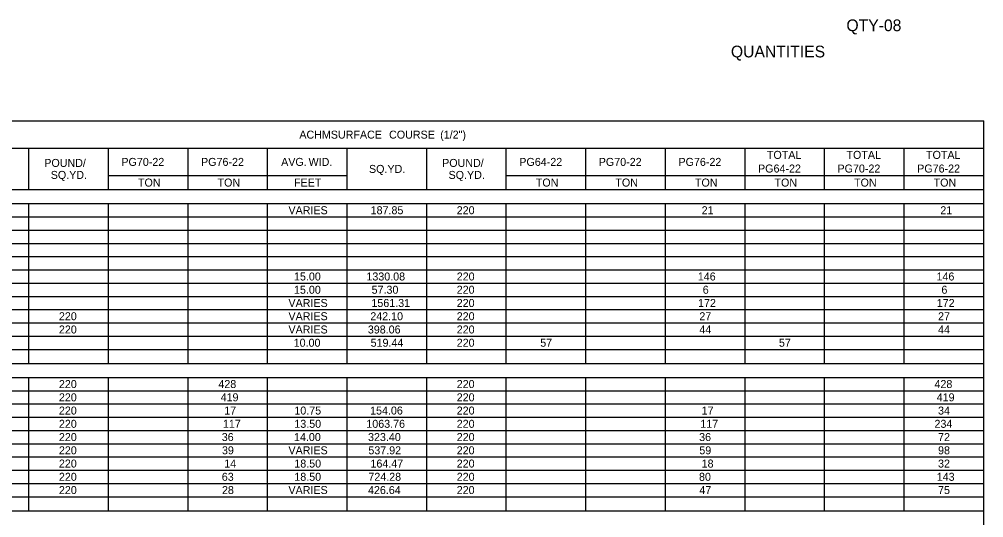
# Model space of a CAD drawing. Extents: x 1226567 to 1228151, y 151309 to 152305.
# Drawn here: x 1227669.3 to 1228150.8, y 152056.4 to 152305.5 of the extents above; entities that cross this region are included whole.
import ezdxf

# ---------------------------------------------------------------- set-up
doc = ezdxf.new("R2010")
doc.units = 0
doc.layers.add('R_Border', color=7, linetype='Continuous')
doc.layers.add('R_Dimension', color=7, linetype='Continuous')

msp = doc.modelspace()

# ---------------------------------------------------------------- linework, layer by layer
at = {"layer": 'R_Dimension'}
for p, q in [((1226566.84, 152254.68), (1228150.79, 152254.68)), ((1228150.79, 151664.64), (1228150.79, 152254.68)), ((1226879.58, 152241.04), (1228150.79, 152241.04)), ((1227674.09, 152220.4), (1227674.09, 152241.04)), ((1227713.81, 152220.4), (1227713.81, 152241.04)), ((1227753.54, 152220.4), (1227753.54, 152241.04)), ((1227793.26, 152220.4), (1227793.26, 152241.04)), ((1227832.99, 152220.4), (1227832.99, 152241.04)), ((1227872.71, 152220.4), (1227872.71, 152241.04)), ((1227912.44, 152220.4), (1227912.44, 152241.04)), ((1227952.16, 152220.4), (1227952.16, 152241.04)), ((1227991.89, 152220.4), (1227991.89, 152241.04)), ((1228031.61, 152220.4), (1228031.61, 152241.04)), ((1228071.34, 152220.4), (1228071.34, 152241.04)), ((1228111.06, 152220.4), (1228111.06, 152241.04)), ((1227713.81, 152227.41), (1227832.99, 152227.41)), ((1227912.44, 152227.41), (1228150.79, 152227.41)), ((1226566.84, 152220.4), (1228150.79, 152220.4)), ((1226566.84, 152220.4), (1228150.79, 152220.4)), ((1227634.36, 152220.4), (1227872.71, 152220.4)), ((1227832.99, 152220.4), (1228150.79, 152220.4)), ((1226566.84, 152213.39), (1228150.79, 152213.39)), ((1227674.09, 152133.55), (1227674.09, 152213.39)), ((1227713.81, 152133.55), (1227713.81, 152213.39)), ((1227753.54, 152133.55), (1227753.54, 152213.39)), ((1227793.26, 152133.55), (1227793.26, 152213.39)), ((1227832.99, 152133.55), (1227832.99, 152213.39)), ((1227872.71, 152133.55), (1227872.71, 152213.39)), ((1227912.44, 152133.55), (1227912.44, 152213.39)), ((1227952.16, 152133.55), (1227952.16, 152213.39)), ((1227991.89, 152133.55), (1227991.89, 152213.39)), ((1228031.61, 152133.55), (1228031.61, 152213.39)), ((1228071.34, 152133.55), (1228071.34, 152213.39)), ((1228111.06, 152133.55), (1228111.06, 152213.39)), ((1226566.84, 152206.77), (1228150.79, 152206.77)), ((1226566.84, 152200.15), (1228150.79, 152200.15)), ((1226566.84, 152193.53), (1228150.79, 152193.53)), ((1226566.84, 152186.91), (1228150.79, 152186.91)), ((1226566.84, 152180.29), (1228150.79, 152180.29)), ((1226566.84, 152173.67), (1228150.79, 152173.67)), ((1226566.84, 152167.05), (1228150.79, 152167.05)), ((1226566.84, 152160.43), (1228150.79, 152160.43)), ((1226566.84, 152153.8), (1228150.79, 152153.8)), ((1226566.84, 152147.18), (1228150.79, 152147.18)), ((1226566.84, 152140.56), (1228150.79, 152140.56)), ((1226566.84, 152133.55), (1228150.79, 152133.55)), ((1226566.84, 152126.54), (1228150.79, 152126.54)), ((1227674.09, 152059.94), (1227674.09, 152126.54)), ((1227713.81, 152059.94), (1227713.81, 152126.54)), ((1227753.54, 152059.94), (1227753.54, 152126.54)), ((1227793.26, 152059.94), (1227793.26, 152126.54)), ((1227832.99, 152059.94), (1227832.99, 152126.54)), ((1227872.71, 152059.94), (1227872.71, 152126.54)), ((1227912.44, 152059.94), (1227912.44, 152126.54)), ((1227952.16, 152059.94), (1227952.16, 152126.54)), ((1227991.89, 152059.94), (1227991.89, 152126.54)), ((1228031.61, 152059.94), (1228031.61, 152126.54)), ((1228071.34, 152059.94), (1228071.34, 152126.54)), ((1228111.06, 152059.94), (1228111.06, 152126.54)), ((1226566.84, 152119.92), (1228150.79, 152119.92)), ((1226566.84, 152113.3), (1228150.79, 152113.3)), ((1226566.84, 152106.68), (1228150.79, 152106.68)), ((1226566.84, 152100.06), (1228150.79, 152100.06)), ((1226566.84, 152093.44), (1228150.79, 152093.44)), ((1226566.84, 152086.82), (1228150.79, 152086.82)), ((1226566.84, 152080.2), (1228150.79, 152080.2)), ((1226566.84, 152073.58), (1228150.79, 152073.58)), ((1226566.84, 152066.95), (1228150.79, 152066.95)), ((1226566.84, 152059.94), (1228150.79, 152059.94))]:
    msp.add_line(p, q, dxfattribs=at)

# ---------------------------------------------------------------- texts
at = {"layer": 'R_Border'}
for s, height, p in [('QTY-08', 5.861, (1228082.24, 152299.55)), ('QUANTITIES', 5.862, (1228024.56, 152286.45))]:
    msp.add_text(s, height=height, dxfattribs=at).set_placement(p)
at = {"layer": 'R_Dimension'}
for s, height, p in [('ACHM', 3.994, (1227809.11, 152245.86)), (' SURFACE', 3.994, (1227823.33, 152245.86)), (' COURSE', 3.994, (1227852.42, 152245.86)), (' (1/2")', 3.994, (1227877.93, 152245.86)), ('POUND', 3.994, (1227681.76, 152231.72)), (' /', 3.994, (1227699.53, 152231.72)), ('PG', 3.994, (1227720.24, 152232.23)), (' 70-22', 3.994, (1227726.5, 152232.23)), ('PG', 3.994, (1227760.03, 152232.23)), (' 76-22', 3.994, (1227766.29, 152232.23)), ('AVG.', 3.994, (1227800.02, 152232.23)), (' WID.', 3.994, (1227812.23, 152232.23)), ('POUND', 3.994, (1227880.39, 152231.72)), (' /', 3.994, (1227898.16, 152231.72)), ('PG', 3.994, (1227918.93, 152232.23)), (' 64-22', 3.994, (1227925.19, 152232.23)), ('PG', 3.994, (1227958.59, 152232.23)), (' 70-22', 3.994, (1227964.85, 152232.23)), ('PG', 3.994, (1227998.38, 152232.23)), (' 76-22', 3.994, (1228004.64, 152232.23)), ('TOTAL', 3.994, (1228042.54, 152235.74)), ('TOTAL', 3.994, (1228082.27, 152235.74)), ('TOTAL', 3.994, (1228121.99, 152235.74)), ('SQ.YD.', 3.994, (1227843.88, 152228.73)), ('PG', 3.994, (1228038.11, 152228.92)), (' 64-22', 3.994, (1228044.37, 152228.92)), ('PG', 3.994, (1228077.77, 152228.92)), (' 70-22', 3.994, (1228084.03, 152228.92)), ('PG', 3.994, (1228117.56, 152228.92)), (' 76-22', 3.994, (1228123.82, 152228.92)), ('SQ.YD.', 3.994, (1227684.98, 152225.73)), ('TON', 3.994, (1227728.53, 152221.91)), ('TON', 3.994, (1227768.26, 152221.91)), ('FEET', 3.994, (1227806.44, 152221.91)), ('SQ.YD.', 3.994, (1227883.61, 152225.73)), ('TON', 3.994, (1227927.16, 152221.91)), ('TON', 3.994, (1227966.88, 152221.91)), ('TON', 3.994, (1228006.61, 152221.91)), ('TON', 3.994, (1228046.33, 152221.91)), ('TON', 3.994, (1228086.06, 152221.91)), ('TON', 3.994, (1228125.78, 152221.91)), ('VARIES', 3.994, (1227803.66, 152208.08)), ('187.85', 3.994, (1227844.7, 152208.08)), ('220', 3.994, (1227887.68, 152208.08)), ('21', 3.994, (1228009.96, 152208.08)), ('21', 3.994, (1228129.13, 152208.08)), ('15.00', 3.994, (1227806.44, 152174.98)), ('1330.08', 3.994, (1227842.59, 152174.98)), ('220', 3.994, (1227887.68, 152174.98)), ('146', 3.994, (1228008.05, 152174.98)), ('146', 3.994, (1228127.23, 152174.98)), ('15.00', 3.994, (1227806.44, 152168.36)), ('57.30', 3.994, (1227845.19, 152168.36)), ('220', 3.994, (1227887.68, 152168.36)), ('6', 3.99, (1228010.51, 152168.36)), ('6', 3.99, (1228129.68, 152168.36)), ('VARIES', 3.994, (1227803.66, 152161.74)), ('1561.31', 3.994, (1227845.08, 152161.74)), ('220', 3.994, (1227887.68, 152161.74)), ('172', 3.994, (1228008.16, 152161.74)), ('172', 3.994, (1228127.34, 152161.74)), ('220', 3.994, (1227689.06, 152155.12)), ('VARIES', 3.994, (1227803.66, 152155.12)), ('242.10', 3.994, (1227844.53, 152155.12)), ('220', 3.994, (1227887.68, 152155.12)), ('27', 3.994, (1228008.82, 152155.12)), ('27', 3.994, (1228128, 152155.12)), ('220', 3.994, (1227689.06, 152148.5)), ('VARIES', 3.994, (1227803.66, 152148.5)), ('398.06', 3.994, (1227843.3, 152148.5)), ('220', 3.994, (1227887.68, 152148.5)), ('44', 3.994, (1228008.82, 152148.5)), ('44', 3.994, (1228128, 152148.5)), ('10.00', 3.994, (1227806.28, 152141.88)), ('519.44', 3.994, (1227844.7, 152141.88)), ('220', 3.994, (1227887.68, 152141.88)), ('57', 3.994, (1227929.37, 152141.88)), ('57', 3.994, (1228048.55, 152141.88)), ('220', 3.994, (1227689.06, 152121.23)), ('428', 3.994, (1227768.68, 152121.23)), ('220', 3.994, (1227887.68, 152121.23)), ('428', 3.994, (1228126.21, 152121.23)), ('220', 3.994, (1227689.06, 152114.61)), ('419', 3.994, (1227769.8, 152114.61)), ('220', 3.994, (1227887.68, 152114.61)), ('419', 3.994, (1228127.32, 152114.61)), ('220', 3.994, (1227689.06, 152107.99)), ('17', 3.994, (1227771.61, 152107.99)), ('10.75', 3.994, (1227806.61, 152107.99)), ('154.06', 3.994, (1227844.43, 152107.99)), ('220', 3.994, (1227887.68, 152107.99)), ('17', 3.994, (1228009.96, 152107.99)), ('34', 3.994, (1228128, 152107.99)), ('220', 3.994, (1227689.06, 152101.37)), ('117', 3.994, (1227770.94, 152101.37)), ('13.50', 3.994, (1227806.6, 152101.37)), ('1063.76', 3.994, (1227842.55, 152101.37)), ('220', 3.994, (1227887.68, 152101.37)), ('117', 3.994, (1228009.3, 152101.37)), ('234', 3.994, (1228126.21, 152101.37)), ('220', 3.994, (1227689.06, 152094.75)), ('36', 3.994, (1227770.36, 152094.75)), ('14.00', 3.994, (1227806.44, 152094.75)), ('323.40', 3.994, (1227843.4, 152094.75)), ('220', 3.994, (1227887.68, 152094.75)), ('36', 3.994, (1228008.71, 152094.75)), ('72', 3.994, (1228128, 152094.75)), ('220', 3.994, (1227689.06, 152088.13)), ('39', 3.994, (1227770.46, 152088.13)), ('VARIES', 3.994, (1227803.66, 152088.13)), ('537.92', 3.994, (1227843.57, 152088.13)), ('220', 3.994, (1227887.68, 152088.13)), ('59', 3.994, (1228008.81, 152088.13)), ('98', 3.994, (1228128, 152088.13)), ('220', 3.994, (1227689.06, 152081.51)), ('14', 3.994, (1227771.61, 152081.51)), ('18.50', 3.994, (1227806.6, 152081.51)), ('164.47', 3.994, (1227844.61, 152081.51)), ('220', 3.994, (1227887.68, 152081.51)), ('18', 3.994, (1228009.96, 152081.51)), ('32', 3.994, (1228128, 152081.51)), ('220', 3.994, (1227689.06, 152074.89)), ('63', 3.994, (1227770.38, 152074.89)), ('18.50', 3.994, (1227806.6, 152074.89)), ('724.28', 3.994, (1227843.57, 152074.89)), ('220', 3.994, (1227887.68, 152074.89)), ('80', 3.994, (1228008.65, 152074.89)), ('143', 3.994, (1228127.34, 152074.89)), ('220', 3.994, (1227689.06, 152068.27)), ('28', 3.994, (1227770.47, 152068.27)), ('VARIES', 3.994, (1227803.66, 152068.27)), ('426.64', 3.994, (1227843.38, 152068.27)), ('220', 3.994, (1227887.68, 152068.27)), ('47', 3.994, (1228008.82, 152068.27)), ('75', 3.994, (1228128, 152068.27))]:
    msp.add_text(s, height=height, dxfattribs=at).set_placement(p)

doc.saveas('drawing.dxf')
